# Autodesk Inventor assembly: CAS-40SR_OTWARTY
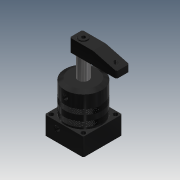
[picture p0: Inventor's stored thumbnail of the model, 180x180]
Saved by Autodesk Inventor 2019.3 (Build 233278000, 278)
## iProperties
Created: 2009-09
Part Number: CAS-40SR_OTWARTY
Material: Ogólny
Document SubType Name: Assembly
Designer: CADENGINEERING4
Sending System: PRO/ENGINEER BY PARAMETRIC TECHNOLOGY CORPORATION, 2007170
Preprocessor: PRO/ENGINEER BY PARAMETRIC TECHNOLOGY CORPORATION, 2007170
Title: CAS-40S_ASM
Author: Administrator
Revision Number: 2LAST_VERSION
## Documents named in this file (7)
- D:\Vault_2016\Projekty\STRONA\Pneumatic\Line ; Pipe connecct - type\cas-40s_asm\CAS-40SR_OTWARTY.iam
- D:\Vault_2016\Projekty\STRONA\Pneumatic\Line ; Pipe connecct - type\cas-40s_asm\CAS-40BT.ipt
- D:\Vault_2016\Projekty\STRONA\Pneumatic\Line ; Pipe connecct - type\cas-40s_asm\CAS-40HSG.ipt
- D:\Vault_2016\Projekty\STRONA\Pneumatic\Line ; Pipe connecct - type\cas-40s_asm\CAS-40HG.ipt
- D:\Vault_2016\Projekty\STRONA\Pneumatic\Line ; Pipe connecct - type\cas-40s_asm\M4.ipt
- D:\Vault_2016\Projekty\STRONA\Pneumatic\Line ; Pipe connecct - type\cas-40s_asm\CAS-32SYB.ipt
- D:\Vault_2016\Projekty\STRONA\Pneumatic\Line ; Pipe connecct - type\cas-40s_asm\M8LC.ipt
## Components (9 placed, 9 different names)
1. CAS-40BT_0
2. CAS-40HSG_1
3. CAS-40HG_2
4. M4_3
5. M4_4
6. M4_5
7. M4_6
8. CAS-32SYB_7
9. M8LC_8
